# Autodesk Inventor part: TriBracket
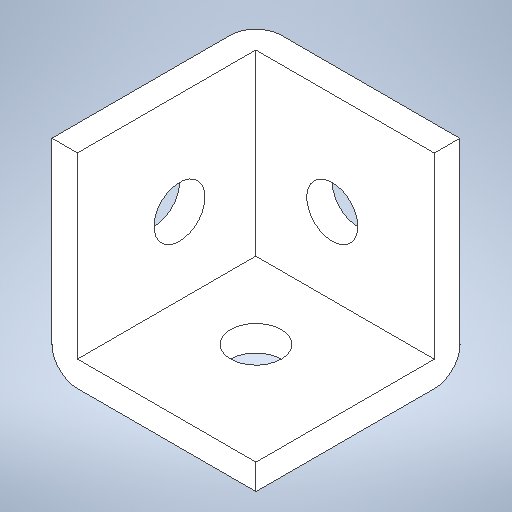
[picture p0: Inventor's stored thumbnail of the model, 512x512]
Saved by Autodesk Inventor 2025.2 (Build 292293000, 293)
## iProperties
Created: 2025-09
Part Number: TriBracket
Material: Generic
Document SubType Name: Modeling
Designer: tyler
Density: 1 g/cm^3
Appearance: Default
Author: tyler
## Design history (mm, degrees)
sketch "Sketch1"
  geometry: L1 (12.7, 12.7)-(-12.7, 12.7); L2 (-12.7, 12.7)-(-12.7, -12.7); L3 (-12.7, -12.7)-(12.7, -12.7); L4 (12.7, -12.7)-(12.7, 12.7); L5 (12.7, 12.7)-(-12.7, -12.7); L6 (-12.7, 12.7)-(12.7, -12.7); 1 further point
  constraints: 12 end point, 2 midpoint, 2 parallel, 1 horizontal, 1 perpendicular
  dimensions: "d0" = 25.4 distance of L3.end L2.end; "d1" = 25.4 distance of L2.end L1.end
extrude "Extrusion1" new body sketch "Sketch1" distance "d2" = 3.175; taper "d3" = 0 deg
sketch "Sketch2"
  geometry: C1 r 3.175 at (0, 0); 1 further point
  constraints: 1 centre point, 1 coincident
  dimensions: "d4" = 6.35 diameter of C1
sketch "Sketch3"
  geometry: L1 (-12.7, 12.7)-(-12.7, -12.7) reference; L2 (-12.7, -12.7)-(-9.525, -12.7); L3 (-12.7, -12.7)-(12.7, -12.7) reference; L4 (-9.525, -12.7)-(-9.525, 12.673); L5 (-9.525, 12.673)-(-9.525, 9.498); L6 (-9.525, 9.498)-(12.7, 9.498); L7 (12.7, 9.498)-(12.7, 12.673); L8 (12.7, 12.673)-(-12.7, 12.673); L9 (-12.7, 12.673)-(-12.7, -12.7); 2 further points
  constraints: 14 end point, 5 perpendicular, 2 point on line
  dimensions: "d5" = 3.175 distance of L1.end L2.end; "d6" = 3.175 distance of L4.end L5.end
extrude "Extrusion2" join sketch "Sketch3" distance "d7" = 22.225; taper "d8" = 0 deg
sketch "Sketch4"
  geometry: L1 (25.373, 22.225)-(0, 22.225) reference; L2 (0, 22.225)-(0, 9.525); L3 (0, -3.175)-(0, 22.225) reference; L4 (0, 9.525)-(12.7, 9.525); C1 r 3.175 at (12.7, 9.525); 1 further point
  constraints: 4 end point, 1 centre point, 1 coincident, 1 midpoint, 1 perpendicular
  dimensions: "d9" = 12.7 distance of L1.end L2.end (derived); "d10" = 12.7 distance of L2.end L4.end; "d11" = 6.35 diameter of C1
sketch "Sketch5"
  geometry: L1 (22.225, 0)-(22.225, 22.225) reference; L2 (22.225, 22.225)-(22.225, 9.525); L3 (22.225, 9.525)-(9.525, 9.525); C1 r 3.175 at (9.525, 9.525); 1 further point
  constraints: 4 end point, 1 centre point, 1 coincident, 1 perpendicular, 1 point on line
  dimensions: "d12" = 12.7 distance of L1.end L2.end; "d13" = 12.7 distance of L2.end L3.end; "d14" = 6.35 diameter of C1
extrude "Extrusion3" cut sketch "Sketch4" distance "d15" = 22.225; taper "d16" = 0 deg
extrude "Extrusion4" cut sketch "Sketch5" distance "d17" = 22.225; taper "d18" = 0 deg
extrude "Extrusion5" cut sketch "Sketch2" distance "d19" = 22.225; taper "d20" = 0 deg
fillet "Fillet2" dims "d22" = 3.175
fillet "Fillet3" dims "d23" = 3.175
body "Solid1"
